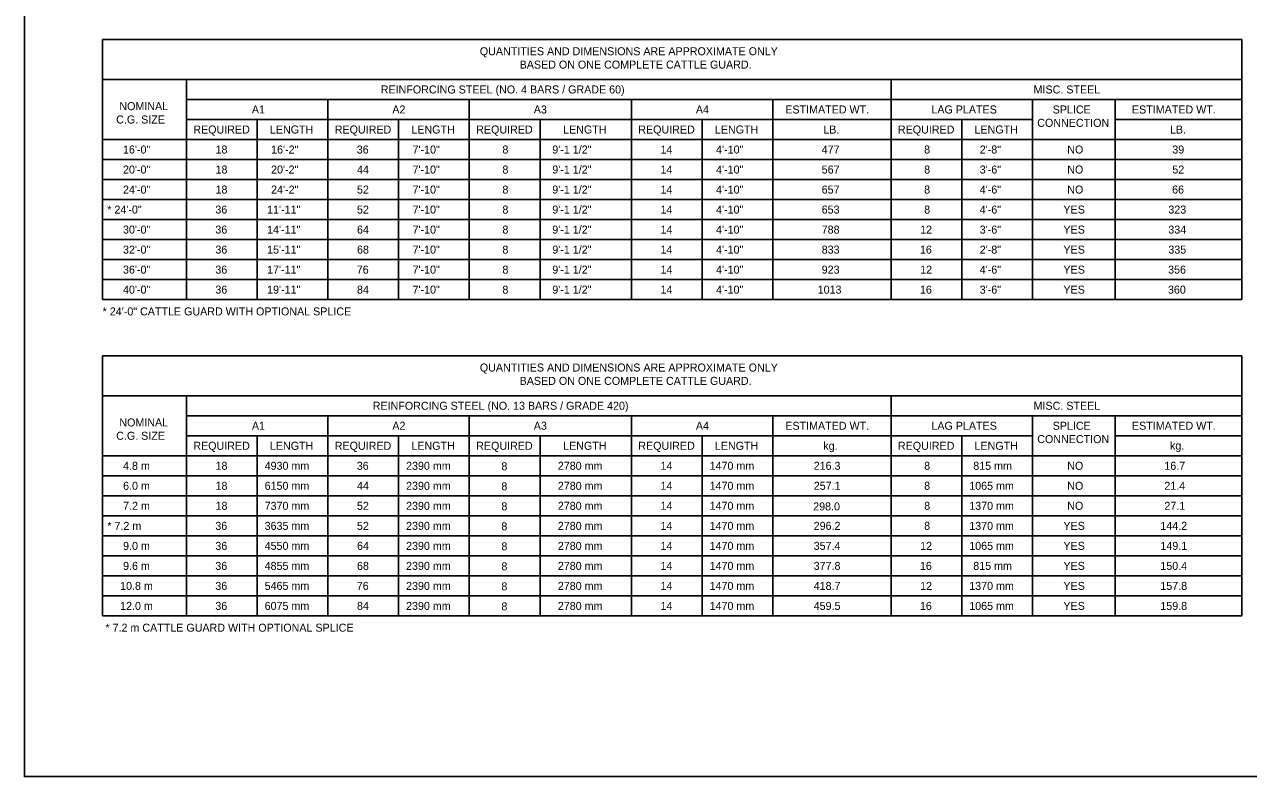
# Model space of a CAD drawing. Extents: x 49987.2 to 50044, y 49982.5 to 50011.4.
# Drawn here: x 49999.38 to 50008.56, y 49987.8 to 49993.43 of the extents above; entities that cross this region are included whole.
import ezdxf

# ---------------------------------------------------------------- set-up
doc = ezdxf.new("R2010")
doc.units = 0
doc.layers.add('Level 1', color=7, linetype='Continuous')
doc.layers.add('Level 2', color=7, linetype='Continuous')

msp = doc.modelspace()

# ---------------------------------------------------------------- linework, layer by layer
at = {"layer": 'Level 1'}
msp.add_lwpolyline([(49999.3835, 49998.9992), (50016.7501, 49998.9992), (50016.7501, 49987.7988), (49999.3835, 49987.7988)], close=True, dxfattribs=at)
at = {"layer": 'Level 2'}
for p, q in [((49999.9676, 49993.3224), (50008.5082, 49993.3224)), ((49999.9676, 49993.3224), (49999.9676, 49991.3724)), ((50008.5082, 49993.3224), (50008.5082, 49991.3724)), ((49999.9676, 49993.0224), (50008.5082, 49993.0224)), ((50000.5976, 49991.3724), (50000.5976, 49993.0224)), ((50005.8786, 49991.3724), (50005.8786, 49993.0224)), ((50000.5976, 49992.8724), (50008.5082, 49992.8724)), ((50001.6576, 49991.3724), (50001.6576, 49992.8724)), ((50002.7176, 49991.3724), (50002.7176, 49992.8724)), ((50003.9326, 49991.3724), (50003.9326, 49992.8724)), ((50004.9926, 49991.3724), (50004.9926, 49992.8724)), ((50006.9386, 49992.8724), (50006.9386, 49991.3724)), ((50007.5591, 49992.8724), (50007.5591, 49991.3724)), ((50000.5976, 49992.7224), (50006.9386, 49992.7224)), ((50001.1276, 49991.3724), (50001.1276, 49992.7224)), ((50002.1876, 49991.3724), (50002.1876, 49992.7224)), ((50003.2476, 49991.3724), (50003.2476, 49992.7224)), ((50004.4626, 49991.3724), (50004.4626, 49992.7224)), ((50006.4086, 49992.7224), (50006.4086, 49991.3724)), ((50007.5591, 49992.7224), (50008.5082, 49992.7224)), ((49999.9676, 49992.5724), (50008.5082, 49992.5724)), ((49999.9676, 49992.4224), (50008.5082, 49992.4224)), ((49999.9676, 49992.2724), (50008.5082, 49992.2724)), ((49999.9676, 49992.1224), (50008.5082, 49992.1224)), ((49999.9676, 49991.9724), (50008.5082, 49991.9724)), ((49999.9676, 49991.8224), (50008.5082, 49991.8224)), ((49999.9676, 49991.6724), (50008.5082, 49991.6724)), ((49999.9676, 49991.5224), (50008.5082, 49991.5224)), ((49999.9676, 49991.3724), (50008.5082, 49991.3724)), ((49999.9676, 49990.9523), (50008.5082, 49990.9523)), ((49999.9676, 49990.9523), (49999.9676, 49989.0023)), ((50008.5082, 49990.9523), (50008.5082, 49989.0023)), ((49999.9676, 49990.6523), (50008.5082, 49990.6523)), ((50000.5976, 49989.0023), (50000.5976, 49990.6523)), ((50005.8786, 49989.0023), (50005.8786, 49990.6523)), ((50000.5976, 49990.5023), (50008.5082, 49990.5023)), ((50001.6576, 49989.0023), (50001.6576, 49990.5023)), ((50002.7176, 49989.0023), (50002.7176, 49990.5023)), ((50003.9326, 49989.0023), (50003.9326, 49990.5023)), ((50004.9926, 49989.0023), (50004.9926, 49990.5023)), ((50006.9386, 49990.5023), (50006.9386, 49989.0023)), ((50007.5591, 49990.5023), (50007.5591, 49989.0023)), ((50000.5976, 49990.3523), (50006.9386, 49990.3523)), ((50001.1276, 49989.0023), (50001.1276, 49990.3523)), ((50002.1876, 49989.0023), (50002.1876, 49990.3523)), ((50003.2476, 49989.0023), (50003.2476, 49990.3523)), ((50004.4626, 49989.0023), (50004.4626, 49990.3523)), ((50006.4086, 49990.3523), (50006.4086, 49989.0023)), ((50007.5591, 49990.3523), (50008.5082, 49990.3523)), ((49999.9676, 49990.2023), (50008.5082, 49990.2023)), ((49999.9676, 49990.0523), (50008.5082, 49990.0523)), ((49999.9676, 49989.9023), (50008.5082, 49989.9023)), ((49999.9676, 49989.7523), (50008.5082, 49989.7523)), ((49999.9676, 49989.6023), (50008.5082, 49989.6023)), ((49999.9676, 49989.4523), (50008.5082, 49989.4523)), ((49999.9676, 49989.3023), (50008.5082, 49989.3023)), ((49999.9676, 49989.1523), (50008.5082, 49989.1523)), ((49999.9676, 49989.0023), (50008.5082, 49989.0023))]:
    msp.add_line(p, q, dxfattribs=at)

# ---------------------------------------------------------------- texts
for s, p in [('QUANTITIES AND DIMENSIONS ARE APPROXIMATE ONLY', (50002.7963, 49993.2038)), ('BASED ON ONE COMPLETE CATTLE GUARD.', (50003.0946, 49993.1038)), ('REINFORCING STEEL (NO. 4 BARS / GRADE 60)', (50002.0536, 49992.9174)), ('MISC. STEEL', (50006.9468, 49992.9174)), ('NOMINAL', (50000.0946, 49992.7924)), ('A1', (50001.0879, 49992.7674)), ('A2', (50002.1406, 49992.7674)), ('A3', (50003.2006, 49992.7674)), ('A4', (50004.4156, 49992.7674)), ('ESTIMATED WT.', (50005.0858, 49992.7674)), ('LAG PLATES', (50006.1809, 49992.7674)), ('SPLICE', (50007.0898, 49992.7674)), ('ESTIMATED WT.', (50007.6839, 49992.7674)), ('C.G. SIZE', (50000.0709, 49992.6924)), ('REQUIRED', (50000.6489, 49992.6174)), ('LENGTH', (50001.223, 49992.6174)), ('REQUIRED', (50001.7089, 49992.6174)), ('LENGTH', (50002.283, 49992.6174)), ('REQUIRED', (50002.7689, 49992.6174)), ('LENGTH', (50003.4205, 49992.6174)), ('REQUIRED', (50003.9839, 49992.6174)), ('LENGTH', (50004.558, 49992.6174)), ('LB.', (50005.3708, 49992.6174)), ('REQUIRED', (50005.9299, 49992.6174)), ('LENGTH', (50006.504, 49992.6174)), ('CONNECTION', (50006.9741, 49992.6674)), ('LB.', (50007.9689, 49992.6174)), ('16\'-0"', (50000.122, 49992.4674)), ('18', (50000.8156, 49992.4674)), ('16\'-2"', (50001.232, 49992.4674)), ('36', (50001.8739, 49992.4674)), ('7\'-10"', (50002.292, 49992.4674)), ('8', (50002.9656, 49992.4674)), ('9\'-1 1/2"', (50003.3395, 49992.4674)), ('14', (50004.1506, 49992.4674)), ('4\'-10"', (50004.567, 49992.4674)), ('477', (50005.3586, 49992.4674)), ('8', (50006.1266, 49992.4674)), ('2\'-8"', (50006.543, 49992.4674)), ('NO', (50007.199, 49992.4674)), ('39', (50007.9864, 49992.4674)), ('20\'-0"', (50000.122, 49992.3174)), ('18', (50000.8156, 49992.3174)), ('20\'-2"', (50001.232, 49992.3174)), ('44', (50001.8756, 49992.3174)), ('7\'-10"', (50002.292, 49992.3174)), ('8', (50002.9656, 49992.3174)), ('9\'-1 1/2"', (50003.3395, 49992.3174)), ('14', (50004.1506, 49992.3174)), ('4\'-10"', (50004.567, 49992.3174)), ('567', (50005.3586, 49992.3174)), ('8', (50006.1266, 49992.3174)), ('3\'-6"', (50006.543, 49992.3174)), ('NO', (50007.199, 49992.3174)), ('52', (50007.9867, 49992.3174)), ('24\'-0"', (50000.122, 49992.1674)), ('18', (50000.8156, 49992.1674)), ('24\'-2"', (50001.232, 49992.1674)), ('52', (50001.8756, 49992.1674)), ('7\'-10"', (50002.292, 49992.1674)), ('8', (50002.9656, 49992.1674)), ('9\'-1 1/2"', (50003.3395, 49992.1674)), ('14', (50004.1506, 49992.1674)), ('4\'-10"', (50004.567, 49992.1674)), ('657', (50005.3586, 49992.1674)), ('8', (50006.1266, 49992.1674)), ('4\'-6"', (50006.543, 49992.1674)), ('NO', (50007.199, 49992.1674)), ('66', (50007.985, 49992.1674)), ('* 24\'-0"', (50000.0041, 49992.0174)), ('36', (50000.8139, 49992.0174)), ('11\'-11"', (50001.202, 49992.0174)), ('52', (50001.8756, 49992.0174)), ('7\'-10"', (50002.292, 49992.0174)), ('8', (50002.9656, 49992.0174)), ('9\'-1 1/2"', (50003.3395, 49992.0174)), ('14', (50004.1506, 49992.0174)), ('4\'-10"', (50004.567, 49992.0174)), ('653', (50005.3586, 49992.0174)), ('8', (50006.1266, 49992.0174)), ('4\'-6"', (50006.543, 49992.0174)), ('YES', (50007.1704, 49992.0174)), ('323', (50007.9567, 49992.0174)), ('9\'-1 1/2"', (50003.3395, 49991.8674)), ('30\'-0"', (50000.122, 49991.8674)), ('36', (50000.8139, 49991.8674)), ('14\'-11"', (50001.202, 49991.8674)), ('64', (50001.8756, 49991.8674)), ('7\'-10"', (50002.292, 49991.8674)), ('8', (50002.9656, 49991.8674)), ('14', (50004.1506, 49991.8674)), ('4\'-10"', (50004.567, 49991.8674)), ('788', (50005.3586, 49991.8674)), ('12', (50006.0966, 49991.8674)), ('3\'-6"', (50006.543, 49991.8674)), ('YES', (50007.1704, 49991.8674)), ('334', (50007.9567, 49991.8674)), ('32\'-0"', (50000.122, 49991.7174)), ('36', (50000.8139, 49991.7174)), ('15\'-11"', (50001.202, 49991.7174)), ('68', (50001.8756, 49991.7174)), ('7\'-10"', (50002.292, 49991.7174)), ('8', (50002.9656, 49991.7174)), ('9\'-1 1/2"', (50003.3395, 49991.7174)), ('14', (50004.1506, 49991.7174)), ('4\'-10"', (50004.567, 49991.7174)), ('833', (50005.3586, 49991.7174)), ('16', (50006.0949, 49991.7174)), ('2\'-8"', (50006.543, 49991.7174)), ('YES', (50007.1704, 49991.7174)), ('335', (50007.9567, 49991.7174)), ('36\'-0"', (50000.122, 49991.5674)), ('36', (50000.8139, 49991.5674)), ('17\'-11"', (50001.202, 49991.5674)), ('76', (50001.8739, 49991.5674)), ('7\'-10"', (50002.292, 49991.5674)), ('8', (50002.9656, 49991.5674)), ('9\'-1 1/2"', (50003.3395, 49991.5674)), ('14', (50004.1506, 49991.5674)), ('4\'-10"', (50004.567, 49991.5674)), ('923', (50005.3586, 49991.5674)), ('12', (50006.0966, 49991.5674)), ('4\'-6"', (50006.543, 49991.5674)), ('YES', (50007.1704, 49991.5674)), ('356', (50007.955, 49991.5674)), ('40\'-0"', (50000.122, 49991.4174)), ('36', (50000.8139, 49991.4174)), ('19\'-11"', (50001.202, 49991.4174)), ('84', (50001.8756, 49991.4174)), ('7\'-10"', (50002.292, 49991.4174)), ('8', (50002.9656, 49991.4174)), ('9\'-1 1/2"', (50003.3395, 49991.4174)), ('14', (50004.1506, 49991.4174)), ('4\'-10"', (50004.567, 49991.4174)), ('1013', (50005.3286, 49991.4174)), ('16', (50006.0949, 49991.4174)), ('3\'-6"', (50006.543, 49991.4174)), ('YES', (50007.1704, 49991.4174)), ('360', (50007.9537, 49991.4174)), ('* 24\'-0" CATTLE GUARD WITH OPTIONAL SPLICE', (49999.9695, 49991.2542)), ('QUANTITIES AND DIMENSIONS ARE APPROXIMATE ONLY', (50002.7963, 49990.8337)), ('BASED ON ONE COMPLETE CATTLE GUARD.', (50003.0946, 49990.7337)), ('REINFORCING STEEL (NO. 13 BARS / GRADE 420)', (50001.9936, 49990.5473)), ('MISC. STEEL', (50006.9468, 49990.5473)), ('NOMINAL', (50000.0946, 49990.4223)), ('C.G. SIZE', (50000.0709, 49990.3223)), ('A1', (50001.0879, 49990.3973)), ('A2', (50002.1406, 49990.3973)), ('A3', (50003.2006, 49990.3973)), ('A4', (50004.4156, 49990.3973)), ('ESTIMATED WT.', (50005.0858, 49990.3973)), ('LAG PLATES', (50006.1809, 49990.3973)), ('SPLICE', (50007.0898, 49990.3973)), ('ESTIMATED WT.', (50007.6839, 49990.3973)), ('REQUIRED', (50000.6489, 49990.2473)), ('LENGTH', (50001.223, 49990.2473)), ('REQUIRED', (50001.7089, 49990.2473)), ('LENGTH', (50002.283, 49990.2473)), ('REQUIRED', (50002.7689, 49990.2473)), ('LENGTH', (50003.4205, 49990.2473)), ('REQUIRED', (50003.9839, 49990.2473)), ('LENGTH', (50004.558, 49990.2473)), ('kg.', (50005.3708, 49990.2472)), ('REQUIRED', (50005.9299, 49990.2473)), ('LENGTH', (50006.504, 49990.2473)), ('CONNECTION', (50006.9741, 49990.2973)), ('kg.', (50007.9689, 49990.2484)), ('  4.8 m', (50000.078, 49990.0973)), ('18', (50000.8156, 49990.0973)), ('4930 mm', (50001.1835, 49990.0973)), ('36', (50001.8739, 49990.0973)), ('2390 mm', (50002.2435, 49990.0973)), ('8', (50002.9579, 49990.0938)), ('2780 mm', (50003.381, 49990.0973)), ('14', (50004.1506, 49990.0973)), ('1470 mm', (50004.5185, 49990.0973)), ('216.3', (50005.2986, 49990.0973)), ('8', (50006.1266, 49990.0973)), ('815 mm', (50006.4945, 49990.0973)), ('NO', (50007.199, 49990.0973)), ('16.7', (50007.9267, 49990.0973)), ('  6.0 m', (50000.078, 49989.9473)), ('18', (50000.8156, 49989.9473)), ('6150 mm', (50001.1835, 49989.9473)), ('44', (50001.8756, 49989.9473)), ('2390 mm', (50002.2435, 49989.9473)), ('8', (50002.9579, 49989.9438)), ('2780 mm', (50003.381, 49989.9473)), ('14', (50004.1506, 49989.9473)), ('1470 mm', (50004.5185, 49989.9473)), ('257.1', (50005.2992, 49989.9473)), ('8', (50006.1266, 49989.9473)), ('1065 mm', (50006.4645, 49989.9473)), ('NO', (50007.199, 49989.9473)), ('21.4', (50007.9267, 49989.9473)), ('  7.2 m', (50000.078, 49989.7973)), ('18', (50000.8156, 49989.7973)), ('7370 mm', (50001.1835, 49989.7973)), ('52', (50001.8756, 49989.7973)), ('2390 mm', (50002.2435, 49989.7973)), ('8', (50002.9579, 49989.7938)), ('2780 mm', (50003.381, 49989.7973)), ('14', (50004.1506, 49989.7973)), ('1470 mm', (50004.5185, 49989.7973)), ('298.0', (50005.2949, 49989.793)), ('8', (50006.1266, 49989.7973)), ('1370 mm', (50006.4645, 49989.7973)), ('NO', (50007.199, 49989.7973)), ('27.1', (50007.9272, 49989.7973)), ('  * 7.2 m', (49999.9601, 49989.6472)), ('36', (50000.8139, 49989.6473)), ('3635 mm', (50001.1835, 49989.6473)), ('52', (50001.8756, 49989.6473)), ('2390 mm', (50002.2435, 49989.6473)), ('8', (50002.9579, 49989.6438)), ('2780 mm', (50003.381, 49989.6473)), ('14', (50004.1506, 49989.6473)), ('1470 mm', (50004.5185, 49989.6473)), ('296.2', (50005.2986, 49989.6473)), ('8', (50006.1266, 49989.6473)), ('1370 mm', (50006.4645, 49989.6473)), ('YES', (50007.1704, 49989.6473)), ('144.2', (50007.8967, 49989.6473)), ('  9.0 m', (50000.078, 49989.4973)), ('36', (50000.8139, 49989.4973)), ('4550 mm', (50001.1835, 49989.4973)), ('64', (50001.8756, 49989.4973)), ('2390 mm', (50002.2435, 49989.4973)), ('8', (50002.9579, 49989.4938)), ('2780 mm', (50003.381, 49989.4973)), ('14', (50004.1506, 49989.4973)), ('1470 mm', (50004.5185, 49989.4973)), ('357.4', (50005.2986, 49989.4973)), ('12', (50006.0966, 49989.4973)), ('1065 mm', (50006.4645, 49989.4973)), ('YES', (50007.1704, 49989.4973)), ('149.1', (50007.8972, 49989.4973)), ('  9.6 m', (50000.078, 49989.3473)), ('36', (50000.8139, 49989.3473)), ('4855 mm', (50001.1835, 49989.3473)), ('68', (50001.8756, 49989.3473)), ('2390 mm', (50002.2435, 49989.3473)), ('8', (50002.9579, 49989.3438)), ('2780 mm', (50003.381, 49989.3473)), ('14', (50004.1506, 49989.3473)), ('1470 mm', (50004.5185, 49989.3473)), ('377.8', (50005.2986, 49989.3473)), ('16', (50006.0949, 49989.3473)), ('815 mm', (50006.4945, 49989.3473)), ('YES', (50007.1704, 49989.3473)), ('150.4', (50007.8968, 49989.3473)), (' 10.8 m', (50000.078, 49989.1973)), ('36', (50000.8139, 49989.1973)), ('5465 mm', (50001.1835, 49989.1973)), ('76', (50001.8739, 49989.1973)), ('2390 mm', (50002.2435, 49989.1973)), ('8', (50002.9579, 49989.1938)), ('2780 mm', (50003.381, 49989.1973)), ('14', (50004.1506, 49989.1973)), ('1470 mm', (50004.5185, 49989.1973)), ('418.7', (50005.2986, 49989.1973)), ('12', (50006.0966, 49989.1973)), ('1370 mm', (50006.4645, 49989.1973)), ('YES', (50007.1704, 49989.1973)), ('157.8', (50007.8967, 49989.1973)), (' 12.0 m', (50000.078, 49989.0473)), ('36', (50000.8139, 49989.0473)), ('6075 mm', (50001.1835, 49989.0473)), ('84', (50001.8756, 49989.0473)), ('2390 mm', (50002.2435, 49989.0473)), ('8', (50002.9579, 49989.0438)), ('2780 mm', (50003.381, 49989.0473)), ('14', (50004.1506, 49989.0473)), ('1470 mm', (50004.5185, 49989.0473)), ('459.5', (50005.2986, 49989.0473)), ('16', (50006.0949, 49989.0473)), ('1065 mm', (50006.4645, 49989.0473)), ('YES', (50007.1704, 49989.0473)), ('159.8', (50007.8967, 49989.0473)), ('* 7.2 m CATTLE GUARD WITH OPTIONAL SPLICE', (49999.9905, 49988.8841))]:
    msp.add_text(s, height=0.06, dxfattribs=at).set_placement(p)

doc.saveas('drawing.dxf')
